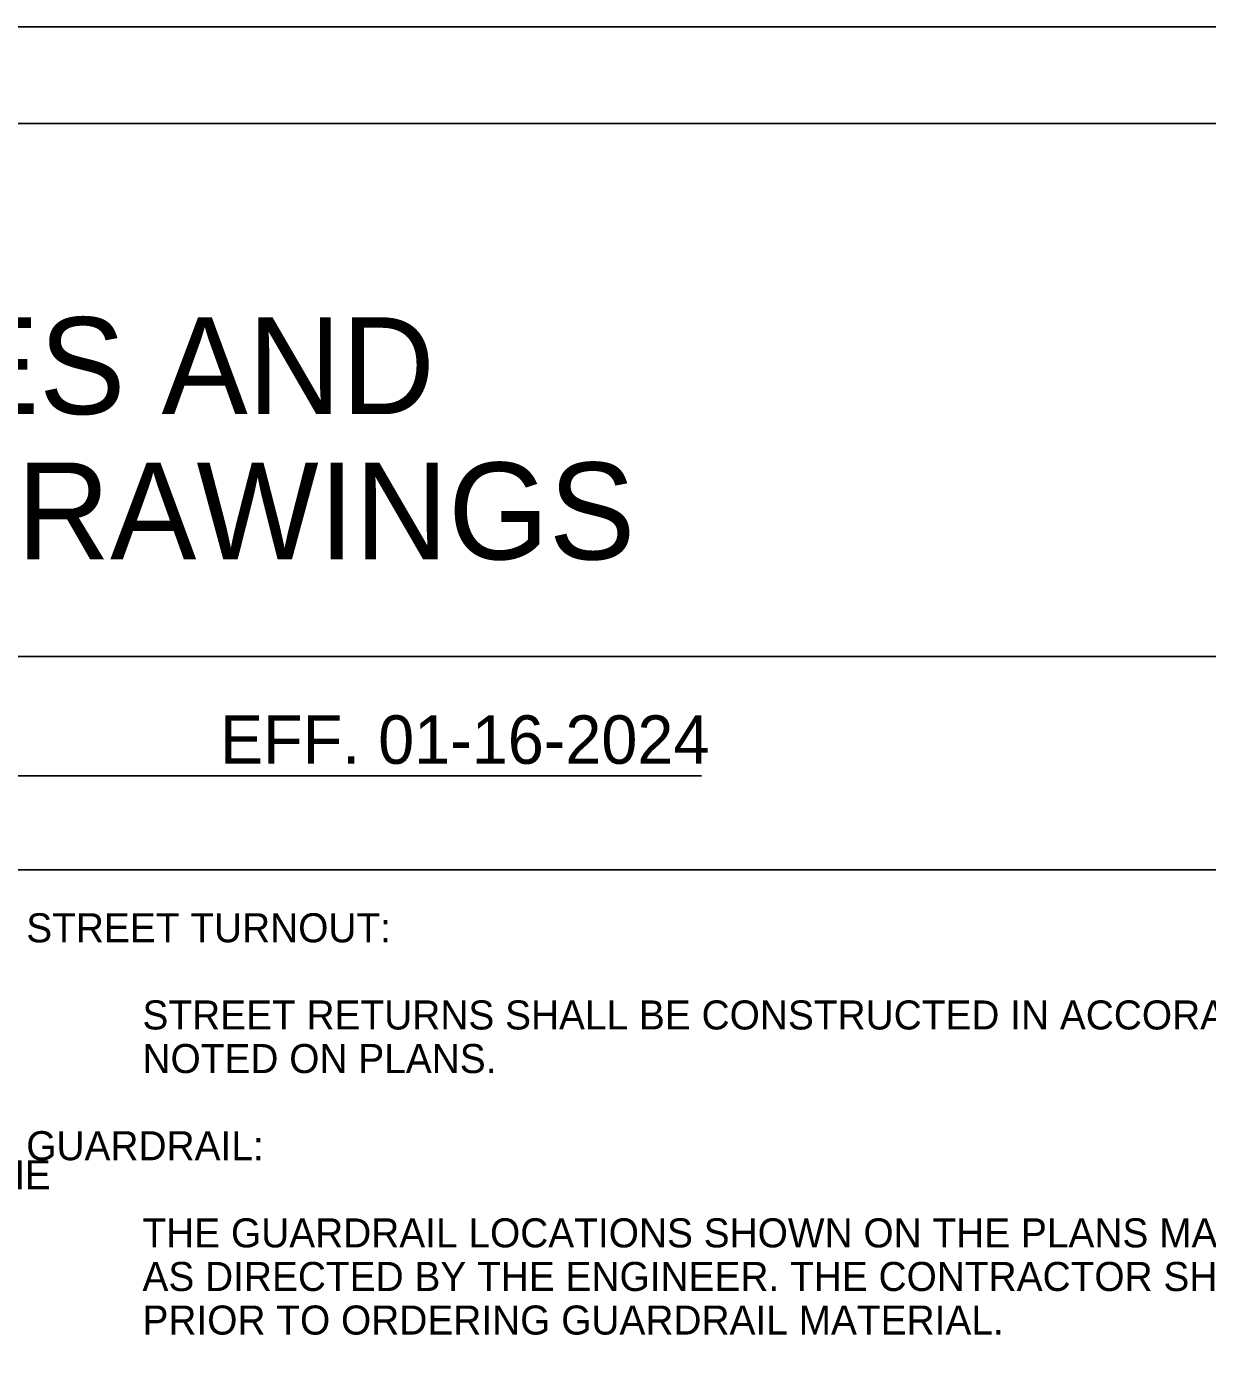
# Model space of a CAD drawing. Extents: x 573076.3 to 573113.7, y -55253.8 to -55199.3.
# Drawn here: x 573100.52 to 573106.61, y -55206.19 to -55199.3 of the extents above; entities that cross this region are included whole.
import ezdxf

# ---------------------------------------------------------------- set-up
doc = ezdxf.new("R2010")
doc.units = 0
for name, color, linetype in [('Prop DSN Text', 7, 'Continuous'), ('Scratch_Level_1', 7, 'Continuous'), ('Sheet Data Field CELL', 7, 'Continuous'), ('Sheet Plan CELL', 7, 'Continuous'), ('Sheet Plot Border Inside CELL', 7, 'Continuous')]:
    doc.layers.add(name, color=color, linetype=linetype)

msp = doc.modelspace()

# ---------------------------------------------------------------- linework, layer by layer
at = {"layer": 'Prop DSN Text'}
msp.add_line((573091.5142, -55203.1651), (573104.0014, -55203.1651), dxfattribs=at)
at = {"layer": 'Scratch_Level_1'}
for p, q in [((573111.5139, -55202.5502), (573076.2547, -55202.5502)), ((573082.5142, -55203.6502), (573112.708, -55203.6502))]:
    msp.add_line(p, q, dxfattribs=at)
at = {"layer": 'Sheet Plan CELL'}
msp.add_lwpolyline([(573081.5142, -55199.7984), (573111.5142, -55199.7984), (573111.5142, -55220.7984), (573081.5142, -55220.7984)], close=True, dxfattribs=at)
at = {"layer": 'Sheet Plot Border Inside CELL'}
msp.add_lwpolyline([(573112.0142, -55199.2984), (573078.0142, -55199.2984), (573078.0142, -55221.2984), (573112.0142, -55221.2984)], close=True, dxfattribs=at)

# ---------------------------------------------------------------- texts
at = {"layer": 'Prop DSN Text'}
for s, height, p in [('EFF. 01-16-2024', 0.25, (573101.5142, -55203.1036)), ('STREET TURNOUT:', 0.15, (573100.5142, -55204.0252)), ('STREET RETURNS SHALL BE CONSTRUCTED IN ACCORANCE WITH STD. NO. 848.04 USING THE RADII', 0.15, (573101.1142, -55204.4752)), ('NOTED ON PLANS.', 0.15, (573101.1142, -55204.7002)), ('GUARDRAIL:', 0.15, (573100.5142, -55205.1502)), ('PROPOSED RESURFACING WILL BE PLACED. GRADE LINES MAY BE ADJUSTED BY THE', 0.15, (573092.1142, -55205.3002)), ('THE GUARDRAIL LOCATIONS SHOWN ON THE PLANS MAY BE ADJUSTED DURING CONSTRUCTION', 0.15, (573101.1142, -55205.6002)), ('AS DIRECTED BY THE ENGINEER. THE CONTRACTOR SHOULD CONSULT WITH THE ENGINEER', 0.15, (573101.1142, -55205.8252)), ('PRIOR TO ORDERING GUARDRAIL MATERIAL.', 0.15, (573101.1142, -55206.0502))]:
    msp.add_text(s, height=height, dxfattribs=at).set_placement(p)
at = {"layer": 'Sheet Data Field CELL'}
for s, p in [('INDEX OF SHEETS, GENERAL NOTES AND', (573088.952, -55201.2984)), ('2024 ROADWAY ENGLISH STANDARD DRAWINGS', (573087.683, -55202.0484))]:
    msp.add_text(s, height=0.5, dxfattribs=at).set_placement(p)

doc.saveas('drawing.dxf')
